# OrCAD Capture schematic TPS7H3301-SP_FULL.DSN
size D
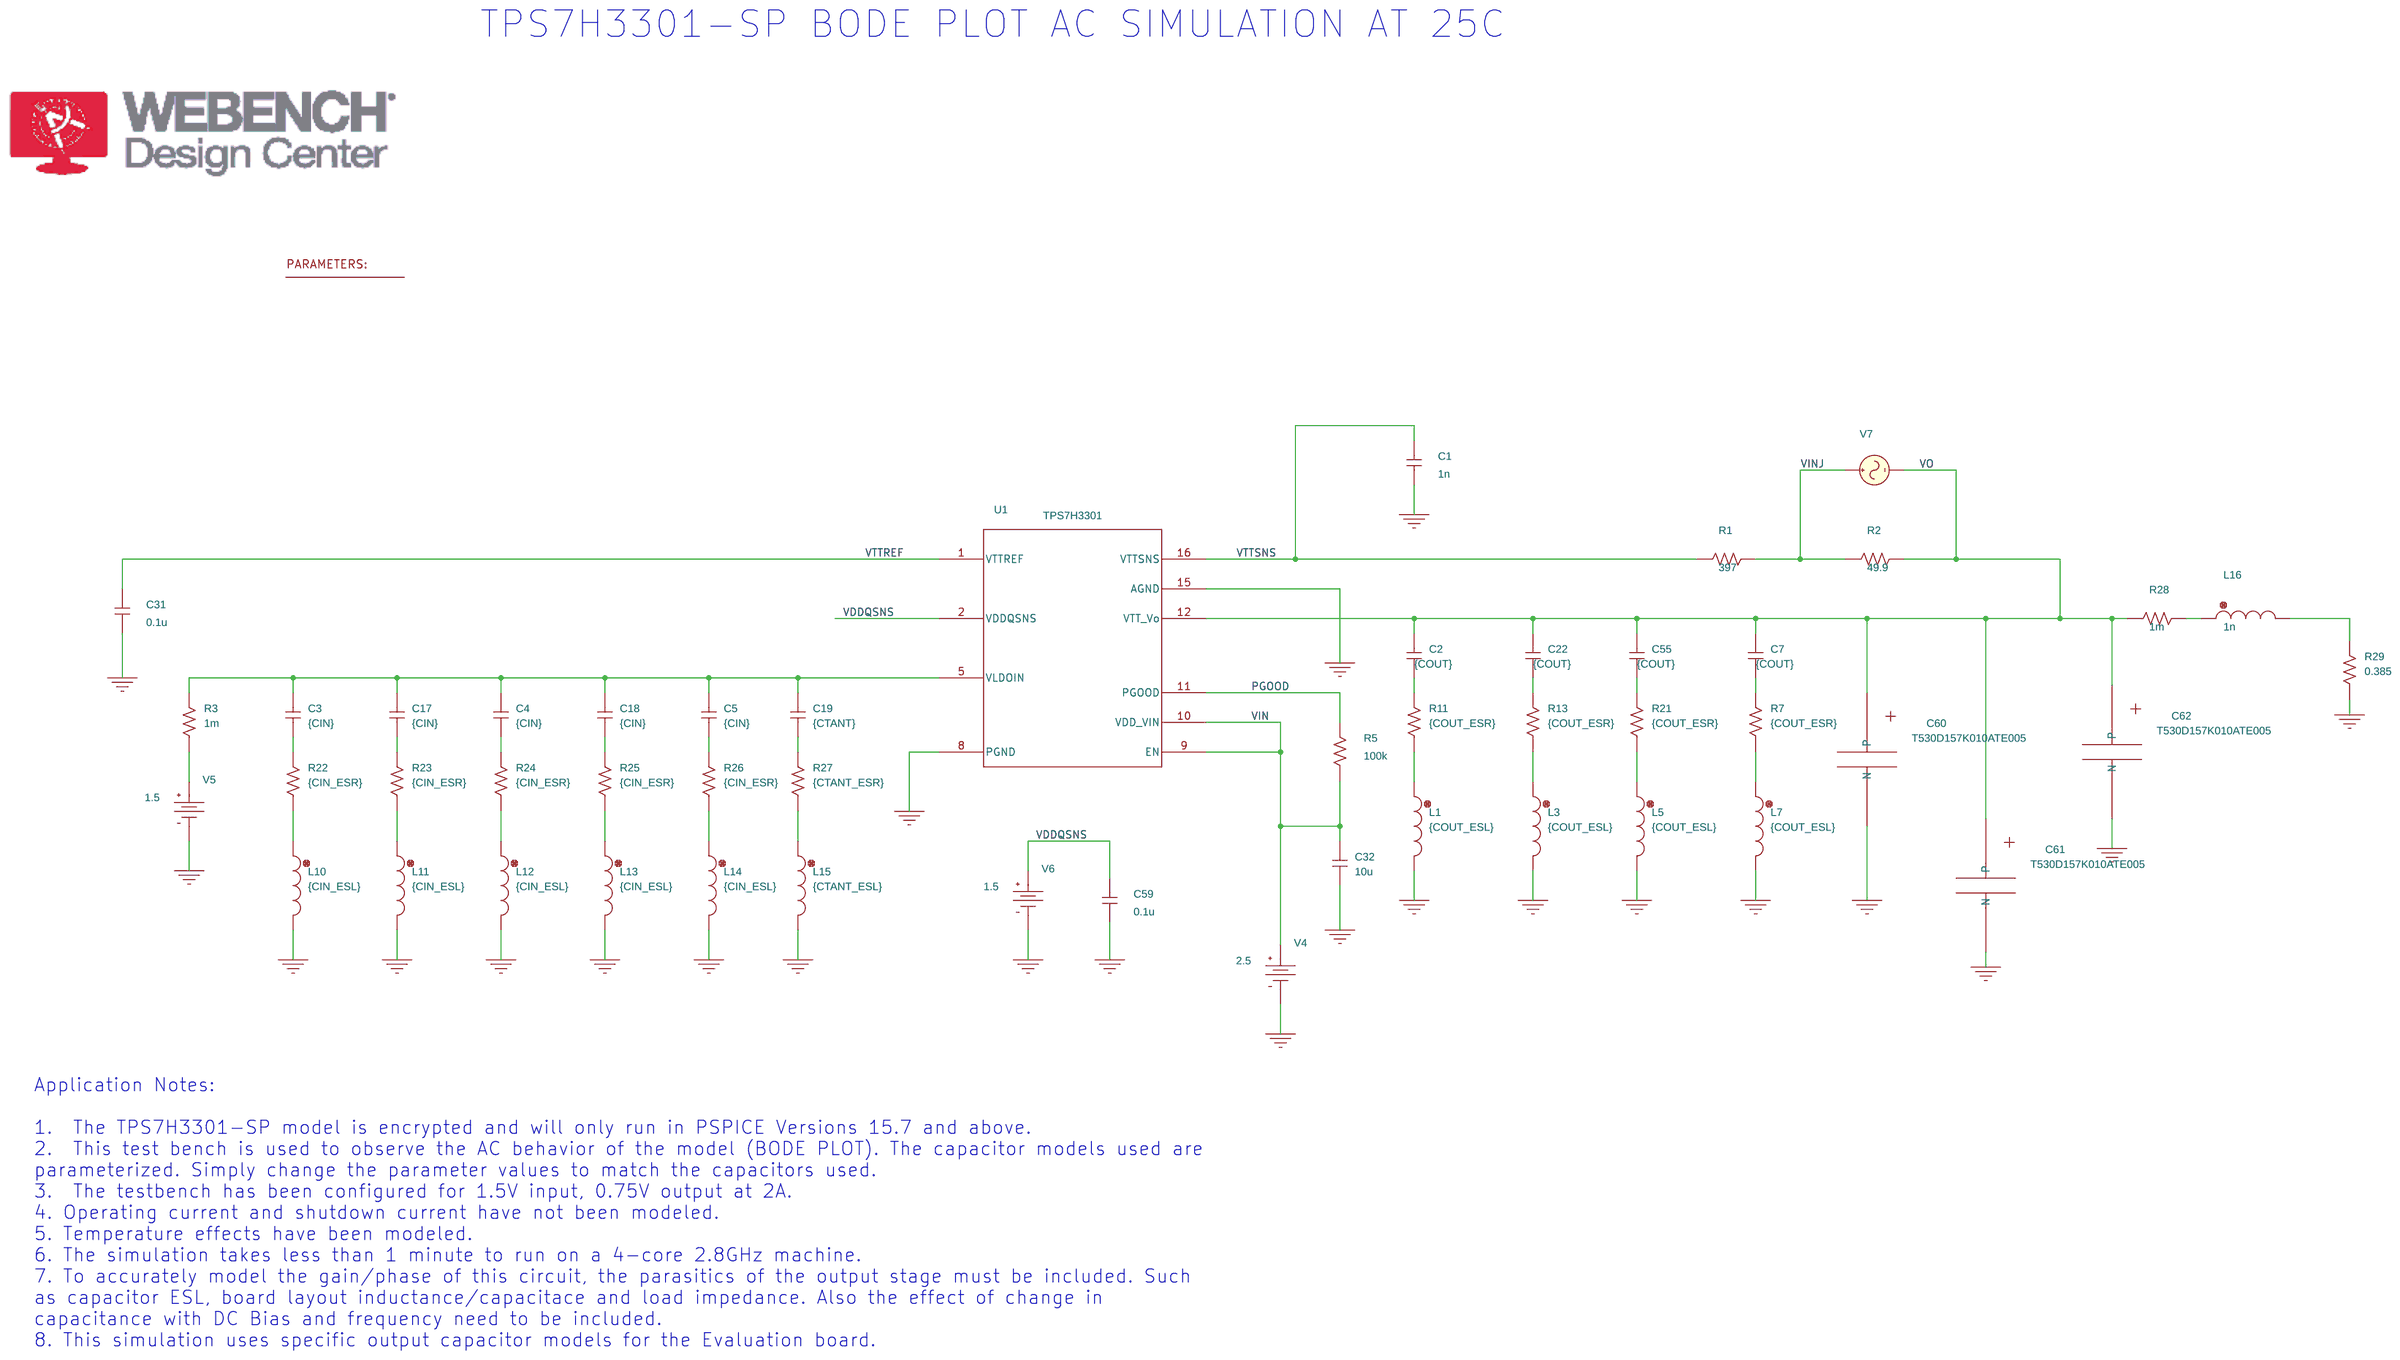
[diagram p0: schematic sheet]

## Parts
1  PARAM
C1  1n  [RAD/CK05]
C2  {COUT}  [RAD/CK05]
C3  {CIN}  [RAD/CK05]
C4  {CIN}  [RAD/CK05]
C5  {CIN}  [RAD/CK05]
C7  {COUT}  [RAD/CK05]
C17  {CIN}  [RAD/CK05]
C18  {CIN}  [RAD/CK05]
C19  {CTANT}  [RAD/CK05]
C22  {COUT}  [RAD/CK05]
C31  0.1u  [RAD/CK05]
C32  10u  [RAD/CK05]
C55  {COUT}  [RAD/CK05]
C59  0.1u  [RAD/CK05]
C60  T530D157K010ATE005
C61  T530D157K010ATE005
C62  T530D157K010ATE005
L1  {COUT_ESL}  [DISC/.350x.175/LS.200x.100/.034]
L3  {COUT_ESL}  [DISC/.350x.175/LS.200x.100/.034]
L5  {COUT_ESL}  [DISC/.350x.175/LS.200x.100/.034]
L7  {COUT_ESL}  [DISC/.350x.175/LS.200x.100/.034]
L10  {CIN_ESL}  [DISC/.350x.175/LS.200x.100/.034]
L11  {CIN_ESL}  [DISC/.350x.175/LS.200x.100/.034]
L12  {CIN_ESL}  [DISC/.350x.175/LS.200x.100/.034]
L13  {CIN_ESL}  [DISC/.350x.175/LS.200x.100/.034]
L14  {CIN_ESL}  [DISC/.350x.175/LS.200x.100/.034]
L15  {CTANT_ESL}  [DISC/.350x.175/LS.200x.100/.034]
L16  1n  [DISC/.350x.175/LS.200x.100/.034]
R1  397  [AX/RC05]
R2  49.9  [AX/RC05]
R3  1m  [AX/RC05]
R5  100k  [AX/RC05]
R7  {COUT_ESR}  [AX/RC05]
R11  {COUT_ESR}  [AX/RC05]
R13  {COUT_ESR}  [AX/RC05]
R21  {COUT_ESR}  [AX/RC05]
R22  {CIN_ESR}  [AX/RC05]
R23  {CIN_ESR}  [AX/RC05]
R24  {CIN_ESR}  [AX/RC05]
R25  {CIN_ESR}  [AX/RC05]
R26  {CIN_ESR}  [AX/RC05]
R27  {CTANT_ESR}  [AX/RC05]
R28  1m  [AX/RC05]
R29  0.385  [AX/RC05]
U1  TPS7H3301
V4  VDC
V5  VDC
V6  VDC
V7  VAC

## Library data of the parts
1 = PARAM: CIN: 10u; CIN_ESL: 1n; CIN_ESR: 2m; COUT: 3.8u; COUT_ESL: 1.1n; COUT_ESR: 6m; CTANT: 150u; CTANT_ESL: 10n; CTANT_ESR: 10m
C1-C5 C7 C17-C19 C22 C31 C32 C55 C59 = C
C60-C62 = T530D157K010ATE005
L1 L3 L5 L7 L10-L16 = L
R1-R3 R5 R7 R11 R13 R21-R29 = R
U1 = TPS7H3301
V4 = VDC: DC: 2.5
V5 V6 = VDC: DC: 1.5
V7 = VAC

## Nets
VDDQSNS: C59.2 U1.2(VDDQSNS) V6.0(+)
VIN: C32.2 R5.1 U1.9(EN) U1.10(VDD_VIN) V4.0(+)
VINJ: R1.2 R2.1 V7.1(+)
0: C1.1 C31.1 C32.1 C59.1 C60.2(N) C61.2(N) C62.2(N) L1.2 L3.2 L5.2 L7.2 L10.2 L11.2 L12.2 L13.2 L14.2 L15.2 R29.1 U1.8(PGND) U1.15(AGND) V4.1(-) V5.1(-) V6.1(-)
PGOOD: R5.2 U1.11(PGOOD)
VO: C2.2 C7.2 C22.2 C55.2 C60.1(P) C61.1(P) C62.1(P) R2.2 R28.1 U1.12(VTT_Vo) V7.2(-)
VTTREF: C31.2 U1.1(VTTREF)
VTTSNS: C1.2 R1.1 U1.16(VTTSNS)
N03102: C3.2 C4.2 C5.2 C17.2 C18.2 C19.2 R3.2 U1.5(VLDOIN)
N07802: R3.1 V5.0(+)
N70006: C7.1 R7.2
N70056: C22.1 R13.2
N70066: C2.1 R11.2
N70080: C55.1 R21.2
N70250: L1.1 R11.1
N70276: L3.1 R13.1
N70282: L5.1 R21.1
N70288: L7.1 R7.1
N70606: L16.2 R29.2
N71681: C3.1 R22.2
N71687: C17.1 R23.2
N71699: L10.1 R22.1
N71705: C4.1 R24.2
N71717: L11.1 R23.1
N71729: L12.1 R24.1
N71741: L13.1 R25.1
N71747: C18.1 R25.2
N71759: L14.1 R26.1
N71765: C5.1 R26.2
N71771: L15.1 R27.1
N71777: C19.1 R27.2
N79252: L16.1 R28.2

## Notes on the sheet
- TPS7H3301-SP BODE PLOT AC SIMULATION AT 25C
- Application Notes:
  1.  The TPS7H3301-SP model is encrypted and will only run in PSPICE Versions 15.7 and above.
  2.  This test bench is used to observe the AC behavior of the model (BODE PLOT). The capacitor models used are
  parameterized. Simply change the parameter values to match the capacitors used.
  3.  The testbench has been configured for 1.5V input, 0.75V output at 2A.
  4. Operating current and shutdown current have not been modeled.
  5. Temperature effects have been modeled.
  6. The simulation takes less than 1 minute to run on a 4-core 2.8GHz machine.
  7. To accurately model the gain/phase of this circuit, the parasitics of the output stage must be included. Such
  as capacitor ESL, board layout inductance/capacitace and load impedance. Also the effect of change in
  capacitance with DC Bias and frequency need to be included.
  8. This simulation uses specific output capacitor models for the Evaluation board.
